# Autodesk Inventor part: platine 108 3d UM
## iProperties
Shininess: 41.0
Angle Display Precision: 2
Document Length Units: 11269
Document Angle Units: 11279
Document Time Units: 11290
Document Mass Units: 11283
Document Length Units Precision: 3
Document Angle Units Precision: 2
Created: 2002-07
Part Number: platine 108 3d UM
Material: Acier doux
Document SubType Name: Modélisation
Designer: jost
Density: 7.860000000000001
Volumn: 626.6980242693378
Area: 1410.1909790998163
PropertySet Name: Model Information
Control State: 0
Master: False
Checked Out: False
Author: jost
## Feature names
1. Extrusion1
2. Perçage1 [Hole]
3. Perçage2 [Hole]
4. Perçage3 [Hole]
